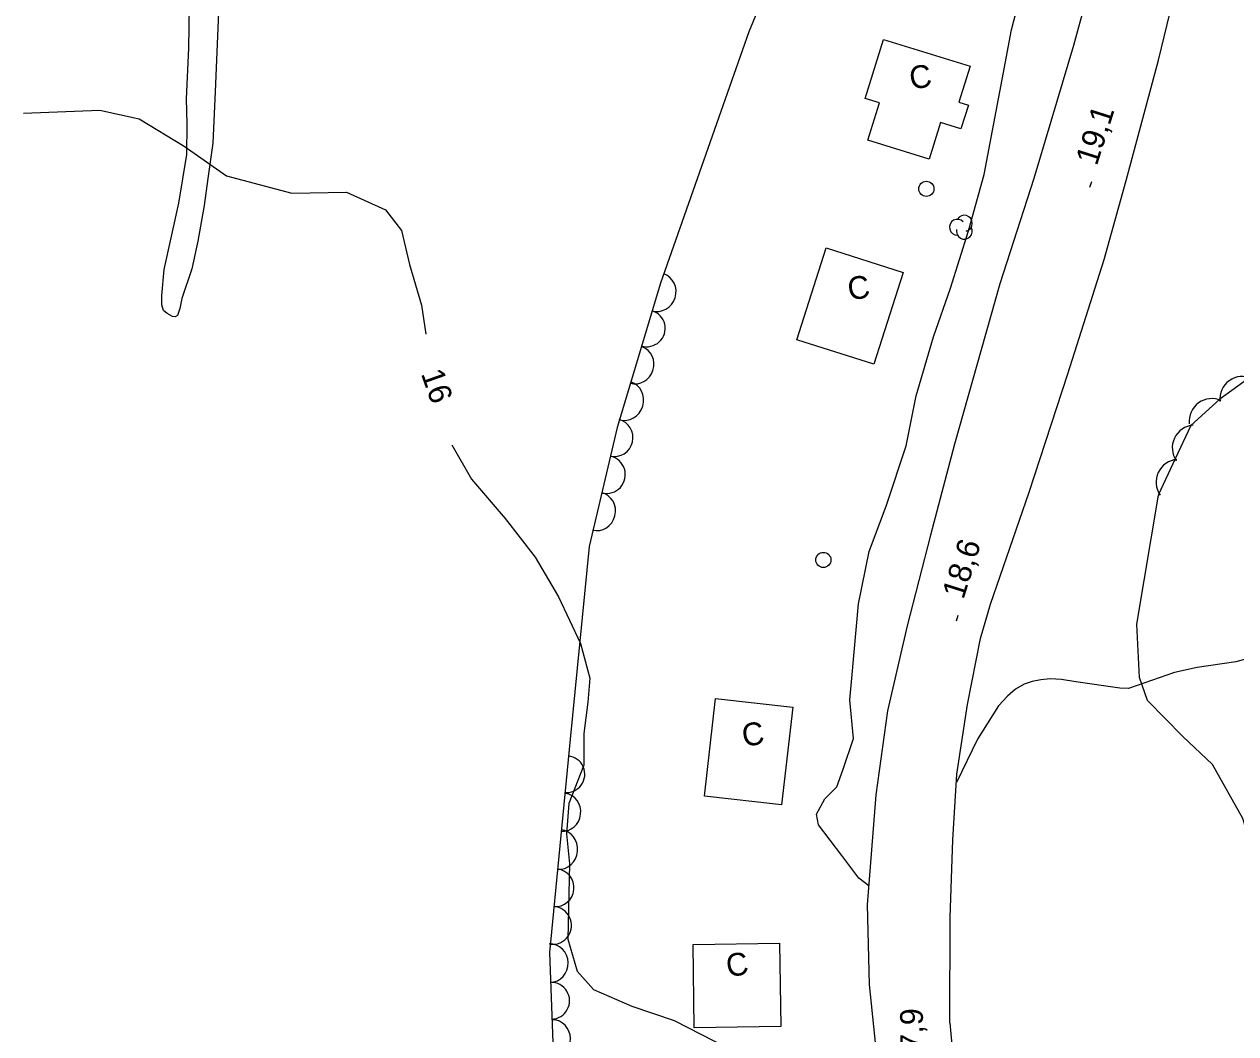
# Model space of a CAD drawing. Extents: x 646142 to 649934, y 5874075 to 5876351.
# Drawn here: x 646574.6 to 646734.2, y 5875454.9 to 5875588 of the extents above; entities that cross this region are included whole.
import ezdxf

# ---------------------------------------------------------------- set-up
doc = ezdxf.new("R2010")
doc.units = 0
for name, color, linetype in [('Niveau 2', 7, 'Continuous'), ('Niveau 21', 7, 'Continuous'), ('Niveau 3', 7, 'Continuous'), ('Niveau 31', 7, 'Continuous'), ('Niveau 36', 7, 'Continuous'), ('Niveau 4', 7, 'Continuous'), ('Niveau 44', 7, 'Continuous')]:
    doc.layers.add(name, color=color, linetype=linetype)

msp = doc.modelspace()

# ---------------------------------------------------------------- linework, layer by layer
at = {"layer": 'Niveau 2'}
for points in [[(646685.82, 5875474.4), (646684.52, 5875475.4), (646682.27, 5875478.38), (646679.21, 5875482.42), (646678.93, 5875483.83), (646680.04, 5875485.88), (646681.6, 5875487.46), (646682.44, 5875489.76), (646683.79, 5875493.8), (646683.33, 5875498.91), (646683.58, 5875501.78), (646684.45, 5875511.57), (646685.88, 5875518.47), (646688.15, 5875524.6), (646690.76, 5875532.4), (646692.05, 5875539), (646694.37, 5875546.76), (646696.61, 5875553.19), (646698.96, 5875560.73), (646701.03, 5875568.17), (646703.39, 5875580.72), (646704.63, 5875587.26), (646706.45, 5875594.39)], [(646574.48, 5875576.26), (646584.53, 5875576.64), (646589.68, 5875575.5), (646595.63, 5875571.89), (646601.2, 5875568.01), (646609.8, 5875565.71), (646617, 5875565.86), (646622.17, 5875563.51), (646624.28, 5875560.79), (646625.31, 5875556.31), (646626.91, 5875550.97), (646627.46, 5875547.14)], [(646630.91, 5875532.55), (646633.48, 5875528.01), (646637.91, 5875522.84), (646641.86, 5875517.73), (646644.95, 5875512.51), (646647.86, 5875506.35), (646649.08, 5875501.79), (646648.8, 5875498.62), (646648.28, 5875494.49), (646648.28, 5875490.31), (646646.3, 5875485.25), (646645.99, 5875481.26), (646646.38, 5875477.3), (646646.17, 5875467.35), (646647.41, 5875463.14), (646649.54, 5875460.73), (646654.61, 5875458.55), (646660.17, 5875456.66), (646667.21, 5875453.04)], [(646738.89, 5875505.2), (646734.16, 5875503.94), (646729.09, 5875503.16), (646726.09, 5875502.51), (646720.06, 5875500.4), (646720.06, 5875500.4)], [(646718.88, 5875500.47), (646713.09, 5875501.27), (646711.2, 5875501.61), (646709.71, 5875501.69), (646708.5, 5875501.56), (646707.33, 5875501.33), (646706.29, 5875500.97), (646705.14, 5875500.31), (646704.08, 5875499.39), (646702.93, 5875498.12), (646700.14, 5875493.73)], [(646720.06, 5875500.4), (646718.88, 5875500.47)], [(646700.14, 5875493.73), (646697.36, 5875488.01)]]:
    msp.add_lwpolyline(points, dxfattribs=at)
at = {"layer": 'Niveau 21'}
for points in [[(646696.48, 5875456.32), (646696.54, 5875470.23), (646696.89, 5875480.47), (646697.43, 5875489.11), (646698.83, 5875498.32), (646700.53, 5875506.99), (646701.87, 5875511.55), (646706.94, 5875526.31), (646712.04, 5875541.88), (646716.85, 5875556.96), (646719.74, 5875567.4), (646724, 5875583.23), (646727.01, 5875595.78), (646730.33, 5875609.65), (646733.7, 5875626.2), (646736.53, 5875634.69)], [(646717.4, 5875602.12), (646712.8, 5875585.2), (646707.58, 5875567.63), (646703.1, 5875553.74), (646697.12, 5875532.61), (646693.94, 5875520.63), (646690.87, 5875508.67), (646688.31, 5875497.46), (646686.77, 5875486.38), (646685.62, 5875471.88), (646685.88, 5875461.37), (646687.29, 5875447.76)], [(646696.48, 5875456.32), (646697.02, 5875450.48)]]:
    msp.add_lwpolyline(points, dxfattribs=at)
at = {"layer": 'Niveau 3'}
for p, q in [((646714.95, 5875566.49), (646715.19, 5875567.25)), ((646697.38, 5875509.33), (646697.62, 5875510.09))]:
    msp.add_line(p, q, dxfattribs=at)
at = {"layer": 'Niveau 31'}
for points in [[(646687.76, 5875585.98), (646699.16, 5875582.45), (646697.69, 5875577.71), (646698.94, 5875577.32), (646697.97, 5875574.19), (646695.27, 5875575.03), (646693.77, 5875570.18), (646685.71, 5875572.68), (646687.25, 5875577.63), (646685.36, 5875578.21), (646687.76, 5875585.98)], [(646676.36, 5875546.39), (646680.22, 5875558.51), (646690.37, 5875555.27), (646686.51, 5875543.15), (646676.36, 5875546.39)], [(646664.17, 5875486.21), (646665.64, 5875499.11), (646675.8, 5875497.96), (646674.33, 5875485.06), (646664.17, 5875486.21)], [(646662.82, 5875455.69), (646662.67, 5875466.68), (646674.07, 5875466.83), (646674.22, 5875455.84), (646662.82, 5875455.69)]]:
    msp.add_lwpolyline(points, dxfattribs=at)
at = {"layer": 'Niveau 36'}
for centre in [(646693.41, 5875566.28), (646679.84, 5875517.36)]:
    msp.add_circle(centre, 1, dxfattribs=at)
at = {"layer": 'Niveau 4'}
for points in [[(646600.2, 5875590.59), (646599.72, 5875579.11), (646599.4, 5875572.31), (646598.74, 5875567.66), (646598.28, 5875564.09), (646597.43, 5875559.37), (646596.62, 5875555.72), (646595.33, 5875551.83), (646595.05, 5875550.53), (646594.73, 5875549.59), (646594.46, 5875549.4), (646594.09, 5875549.44), (646593.39, 5875549.86)], [(646593.39, 5875549.86), (646592.92, 5875550.24), (646592.67, 5875551), (646592.67, 5875552.22), (646593.01, 5875555.64), (646594.94, 5875564.38), (646595.96, 5875570.8), (646596.04, 5875574.86), (646595.93, 5875578.13), (646596.23, 5875584.85), (646596.31, 5875590.42)]]:
    msp.add_lwpolyline(points, dxfattribs=at)
at = {"layer": 'Niveau 44'}
for points in [[(646677.67, 5875616.87), (646674.88, 5875598.79), (646670, 5875587), (646658.39, 5875553.83), (646652.67, 5875534.8), (646648.98, 5875519.15), (646646.46, 5875493.72), (646643.77, 5875465.61), (646644.62, 5875441.87), (646647.99, 5875416.95), (646654.4, 5875393.05), (646655.24, 5875387.16), (646654.57, 5875384.13), (646653.39, 5875381.94), (646648.01, 5875375.2), (646638.78, 5875366.16)], [(646736.01, 5875541.41), (646732.07, 5875538.57), (646728.26, 5875535.09), (646726.18, 5875530.7), (646724.01, 5875526), (646723.94, 5875525.77)], [(646779.26, 5875439.05), (646778.08, 5875442.92), (646773.52, 5875457.37), (646770.94, 5875460.99), (646768.31, 5875462.71), (646766.22, 5875463.05), (646763.54, 5875462.8), (646748.6, 5875459.24), (646744.31, 5875458.6), (646742.74, 5875459.4), (646741.46, 5875461.83), (646739.84, 5875467.44), (646735.12, 5875483.29), (646731.12, 5875490.39), (646727.21, 5875494.09), (646722.53, 5875498.85), (646721.47, 5875501.87), (646721.13, 5875508.88), (646723.98, 5875525.89)]]:
    msp.add_lwpolyline(points, dxfattribs=at)
for centre, radius, start, end in [((646697.51, 5875561.22), 1.05, 44.1154, 269.804), ((646698.41, 5875561.75), 1.05, 282.2692, 149.7263), ((646698.41, 5875560.7), 1.05, 166.9369, 29.6212), ((646735.07, 5875538.56), 3, 65.8496, 185.8275), ((646731.02, 5875535.63), 3, 65.8496, 185.8275), ((646728.81, 5875532.14), 3, 94.6871, 214.6651), ((646726.67, 5875527.62), 3, 94.6871, 214.6651)]:
    msp.add_arc(centre, radius, start, end, dxfattribs=at)
for centre, major_axis, ratio, start_param, end_param in [((646658, 5875552.65), (0.76, 2.43), 0.952628, 3.141593, 6.283185), ((646656.57, 5875547.89), (2.32, -0.72), 0.997449, 4.712389, 7.853982), ((646655.2, 5875543.06), (0.77, 2.38), 0.919919, 3.141593, 6.283185), ((646653.73, 5875538.34), (0.75, 2.49), 0.925819, 3.141593, 6.283185), ((646652.35, 5875533.46), (0.57, 2.41), 0.970147, 3.141593, 6.283185), ((646651.25, 5875528.61), (2.44, -0.53), 0.99999, 4.712389, 7.853982), ((646650.03, 5875523.76), (0.61, 2.47), 0.952628, 3.141593, 6.283185), ((646645.98, 5875489.11), (2.42, -0.26), 0.997449, 4.712389, 7.853982), ((646645.58, 5875484.1), (0.29, 2.48), 0.919919, 3.141593, 6.283185), ((646645.06, 5875479.18), (0.25, 2.59), 0.925819, 3.141593, 6.283185), ((646644.58, 5875474.13), (0.24, 2.46), 0.970147, 3.141593, 6.283185), ((646644.16, 5875469.18), (2.49, -0.19), 0.99999, 4.712389, 7.853982), ((646643.79, 5875464.21), (-0.07, 2.55), 0.952628, 3.141593, 6.283185), ((646643.97, 5875459.24), (2.43, 0.06), 0.997449, 4.712389, 7.853982), ((646644.22, 5875454.22), (-0.04, 2.5), 0.919919, 3.141593, 6.283185)]:
    msp.add_ellipse(centre, major_axis=major_axis, ratio=ratio, start_param=start_param, end_param=end_param, dxfattribs=at)

# ---------------------------------------------------------------- texts
at = {"layer": 'Niveau 2'}
msp.add_text('16', height=3, rotation=289.5164, dxfattribs=at).set_placement((646626.79, 5875541.93))
at = {"layer": 'Niveau 3'}
for s, rotation, p in [('19,1 ', 72.3755, (646715.86, 5875569.22)), ('18,6 ', 72.518, (646698.29, 5875512.06)), ('17,9 ', 90.1276, (646692.97, 5875450.45))]:
    msp.add_text(s, height=3, rotation=rotation, dxfattribs=at).set_placement(p)
at = {"layer": 'Niveau 31'}
for p in [(646691.42, 5875579.36), (646683.28, 5875551.56), (646669.36, 5875492.71), (646667.27, 5875462.34)]:
    msp.add_text('C', height=3, rotation=8.9405, dxfattribs=at).set_placement(p)

doc.saveas('drawing.dxf')
